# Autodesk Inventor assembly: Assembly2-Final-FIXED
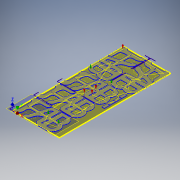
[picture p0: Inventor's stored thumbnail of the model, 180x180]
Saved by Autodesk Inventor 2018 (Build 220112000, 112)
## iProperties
Created: 2018-03
Part Number: Assembly2-Final-FIXED
Document SubType Name: Assembly
Designer: katin
Author: katin
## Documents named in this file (5)
- C:\Users\katin\Documents\FabAcademy2018\+MODEL-FILES\Week 7\+CNC+\Assembly2-Final-FIXED.iam
- C:\Users\katin\Documents\FabAcademy2018\+MODEL-FILES\Week 7\+CNC+\w8-FAB-shelf-holes-1-7.ipt
- C:\Users\katin\Documents\FabAcademy2018\+MODEL-FILES\Week 7\+CNC+\w8-FAB-shelf-holes-4tabs.ipt
- C:\Users\katin\Documents\FabAcademy2018\+MODEL-FILES\Week 7\+CNC+\w8-FAB-shelf-holes-9-Final++.ipt
- C:\Users\katin\Documents\FabAcademy2018\+MODEL-FILES\Week 7\+CNC+\w8-FAB-shelf-holes-10-Final+.ipt
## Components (6 placed, 4 different names)
1. w8-FAB-shelf-holes-1-7:1 — Flush:1, Flush:4
2. w8-FAB-shelf-holes-1-7:2 — Flush:2, Flush:3, Flush:5, Mate:1
3. w8-FAB-shelf-holes-1-7:3 — Flush:2, Mate:1
4. w8-FAB-shelf-holes-9-Final++:1
5. w8-FAB-shelf-holes-10-Final+:1
6. w8-FAB-shelf-holes-4tabs:1
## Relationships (6: Flush 5, Mate 1)
- Flush:1: w8-FAB-shelf-holes-1-7:1
- Flush:2: w8-FAB-shelf-holes-1-7:2 ↔ w8-FAB-shelf-holes-1-7:3
- Flush:3: w8-FAB-shelf-holes-1-7:2
- Flush:4: w8-FAB-shelf-holes-1-7:1
- Flush:5: w8-FAB-shelf-holes-1-7:2
- Mate:1: w8-FAB-shelf-holes-1-7:2 ↔ w8-FAB-shelf-holes-1-7:3
